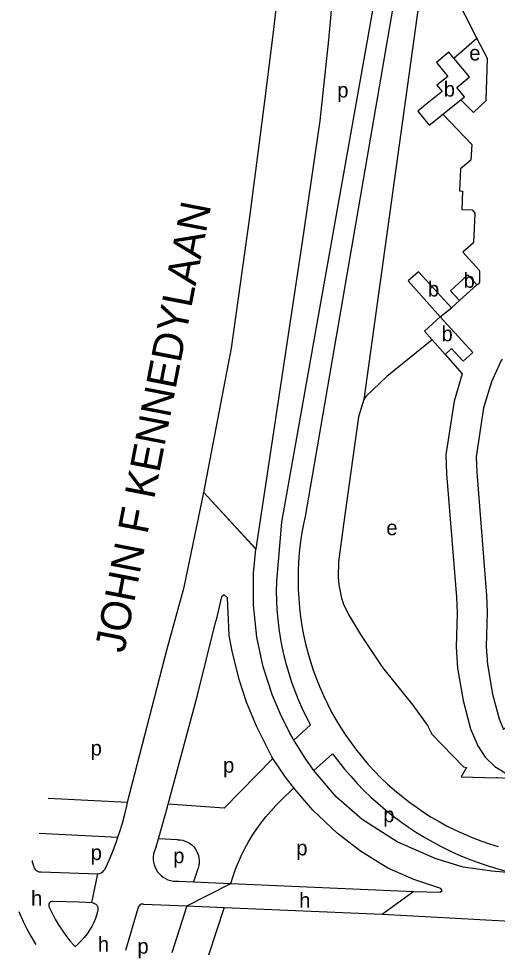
# Model space of a CAD drawing. Extents: x 161773 to 163836, y 384796 to 386521.
# Drawn here: x 161772.9 to 161899.9, y 384853.2 to 385102.4 of the extents above; entities that cross this region are included whole.
import ezdxf

# ---------------------------------------------------------------- set-up
doc = ezdxf.new("R2010")
doc.units = 0
for name, color, linetype in [('BLT_Basislijn', 7, 'Continuous'), ('BLT_Bebouwing', 7, 'Continuous'), ('BLT_Centroide', 7, 'Continuous'), ('BLT_Straatnaam_hoofdweg', 7, 'Continuous'), ('BLT_Vlakafsluiter', 7, 'Continuous')]:
    doc.layers.add(name, color=color, linetype=linetype)

msp = doc.modelspace()

# ---------------------------------------------------------------- linework, layer by layer
at = {"layer": 'BLT_Basislijn'}
for p, q in [((161873.54, 385113.42), (161848.95, 384970.34)), ((161888.38, 385092.02), (161894.55, 385097.32)), ((161889.93, 385027.67), (161887.79, 385025.73)), ((161835.82, 384961.76), (161835.81, 384961.7)), ((161845.96, 384911.03), (161850.33, 384915.09)), ((161851.27, 384903.01), (161856.23, 384907.43)), ((161827.39, 384892.98), (161840.39, 384906.22)), ((161780.74, 384895.67), (161801.8, 384894.59)), ((161827.39, 384892.98), (161812.6, 384894.03)), ((161778.3, 384886.33), (161799.22, 384885.27)), ((161809.4, 384882.73), (161810.01, 384884.88)), ((161815.08, 384884.63), (161810.01, 384884.88)), ((161820.48, 384876.94), (161819.28, 384873.47)), ((161778.81, 384876.1), (161793.91, 384875.57)), ((161815.37, 384873.65), (161819.28, 384873.47)), ((161819.28, 384873.47), (161829.2, 384873.03)), ((161829.2, 384873.03), (161877.83, 384870.87)), ((161806.02, 384867.54), (161817.55, 384867.06)), ((161817.55, 384867.06), (161813.53, 384854.59)), ((161817.55, 384867.06), (161827.45, 384866.65)), ((161827.45, 384866.65), (161823.31, 384853.98)), ((161827.45, 384866.65), (161869.49, 384864.9)), ((161801.3, 384855.35), (161804.59, 384866.47))]:
    msp.add_line(p, q, dxfattribs=at)
for points in [[(161949.14, 385327.14), (161942.55, 385330.53), (161938.43, 385320.55), (161923.2, 385306.75), (161913.58, 385286.21), (161900, 385229.51), (161892.42, 385198.57), (161884.59, 385146.22), (161864.49, 385001.44)], [(161894.55, 385097.32), (161885.32, 385115.47), (161884.66, 385125.98), (161885.84, 385134.74), (161888.36, 385140.63), (161891.73, 385145.18), (161899.3, 385152.42), (161902.89, 385157.22)], [(161857.58, 385124.36), (161855.16, 385096.84), (161852.87, 385075.31), (161848.12, 385043.24), (161835.82, 384961.76)], [(161841.4, 384953.23), (161842.72, 384968.87), (161868.6, 385114.18)], [(161829.37, 385015.04), (161831.79, 385032.09), (161834.13, 385049.14), (161836.4, 385066.2), (161838.58, 385083.28), (161840.69, 385100.36), (161841.72, 385108.98)], [(161890.26, 385080.96), (161893.66, 385077.6), (161896.98, 385080.73), (161897.33, 385091.89), (161894.55, 385097.32)], [(161885.51, 385077.12), (161893.22, 385069.04), (161892.91, 385064.92), (161890.19, 385062.62), (161889.9, 385056.74), (161890.73, 385056.68), (161890.5, 385051.86), (161893.29, 385051.7), (161894.03, 385050.85), (161893.62, 385043.03), (161890.81, 385040.48), (161895.12, 385035.76), (161895.24, 385035.4), (161895.2, 385032.52), (161895.03, 385032.15), (161894.52, 385031.83)], [(161882.69, 385017.21), (161870.64, 385007.53), (161865.04, 385002.24), (161864.49, 385001.44)], [(161822.06, 384976.79), (161829.37, 385015.04)], [(161886.08, 385013.38), (161890.67, 385008.22), (161888.52, 385000.98), (161886.32, 384986.73), (161886.5, 384981.66), (161889.14, 384948.99), (161889.27, 384944.86), (161889.04, 384935.7), (161889.42, 384930.14), (161890.88, 384921.58), (161892.84, 384914.09), (161894.75, 384909.55), (161896.72, 384906.57), (161899.33, 384904.04), (161902.73, 384901.93), (161907.18, 384900.61)], [(161901.22, 385012.12), (161900.86, 385011.6), (161898.39, 385006.11), (161896.34, 384999.22), (161894.34, 384986.25), (161894.49, 384982.12), (161897.13, 384949.44), (161897.27, 384944.89), (161897.04, 384935.87), (161897.37, 384931.09), (161898.71, 384923.27), (161900.44, 384916.67), (161901.61, 384913.87), (161902.51, 384914.77), (161903.09, 384925.99), (161911.95, 384925.55)], [(161864.49, 385001.44), (161863.12, 384996.79), (161859.15, 384968.28)], [(161801.8, 384894.59), (161812.3, 384935.27), (161816.83, 384951.64), (161822.05, 384976.73)], [(161822.05, 384976.73), (161822.06, 384976.79)], [(161848.95, 384970.34), (161848.44, 384967.96), (161848.01, 384965.57), (161847.65, 384963.17), (161847.38, 384960.75), (161847.19, 384958.33), (161847.08, 384955.9), (161847.04, 384953.47), (161847.09, 384951.04), (161847.22, 384948.61), (161847.43, 384946.19), (161847.71, 384943.78), (161848.08, 384941.38), (161848.52, 384938.99), (161849.04, 384936.61), (161849.64, 384934.26), (161850.32, 384931.93), (161851.08, 384929.62), (161851.91, 384927.33), (161852.81, 384925.08), (161853.79, 384922.85), (161854.84, 384920.66), (161855.96, 384918.51), (161857.16, 384916.39), (161858.42, 384914.31), (161859.75, 384912.28), (161861.14, 384910.29), (161862.6, 384908.35), (161864.13, 384906.46), (161865.71, 384904.61), (161867.36, 384902.82), (161869.06, 384901.09), (161870.82, 384899.41), (161872.63, 384897.8), (161874.5, 384896.24), (161876.42, 384894.74), (161878.38, 384893.31), (161880.39, 384891.95), (161882.44, 384890.65), (161884.54, 384889.42), (161886.67, 384888.26), (161888.85, 384887.17), (161891.05, 384886.15), (161893.29, 384885.21), (161895.56, 384884.34), (161897.86, 384883.54), (161900.18, 384882.82)], [(161859.15, 384968.28), (161857.83, 384958.36), (161857.67, 384954.2), (161857.88, 384952.22), (161858.58, 384948.67), (161859.16, 384947.12), (161860.45, 384944.39), (161863.61, 384939.1), (161869.51, 384930.34), (161877.5, 384920.35), (161881.4, 384914.95), (161882.54, 384912.62), (161890.97, 384903.96), (161891.79, 384903.81), (161890.39, 384901.27), (161899.62, 384901.08)], [(161845.96, 384911.03), (161845.76, 384911.36), (161844.79, 384913.07), (161842.35, 384917.91), (161840.3, 384922.92), (161837.83, 384930.54), (161836.12, 384938.37), (161835.21, 384946.82), (161835.19, 384955.31), (161835.81, 384961.7)], [(161850.33, 384915.09), (161849.21, 384917.28), (161848.15, 384919.5), (161847.17, 384921.76), (161846.26, 384924.05), (161845.43, 384926.36), (161844.67, 384928.7), (161843.99, 384931.07), (161843.38, 384933.45), (161842.86, 384935.86), (161842.41, 384938.28), (161842.04, 384940.71), (161841.75, 384943.15), (161841.54, 384945.6), (161841.41, 384948.06), (161841.36, 384950.52), (161841.39, 384952.98), (161841.4, 384953.23)], [(161840.39, 384906.22), (161840.13, 384906.65), (161839.18, 384908.4), (161836.01, 384914.76), (161833.4, 384921.16), (161831.44, 384927.1), (161829.56, 384934.64), (161828.8, 384938.81), (161828.58, 384943.04), (161828.34, 384948.84), (161827.45, 384949.58), (161826.72, 384949.04), (161825.18, 384942.64)], [(161812.6, 384894.03), (161820.25, 384922.61), (161825.18, 384942.64)], [(161851.27, 384903.01), (161849.08, 384905.98), (161846.69, 384909.81), (161845.96, 384911.03)], [(161856.23, 384907.43), (161857.77, 384905.39), (161859.38, 384903.39), (161861.05, 384901.45), (161862.77, 384899.56), (161864.56, 384897.72), (161866.4, 384895.94), (161868.3, 384894.22), (161870.24, 384892.56), (161872.24, 384890.96), (161874.29, 384889.43), (161876.39, 384887.96), (161878.53, 384886.55), (161880.71, 384885.21), (161882.94, 384883.95), (161885.2, 384882.75), (161887.5, 384881.62), (161889.83, 384880.57), (161892.2, 384879.59), (161894.59, 384878.68), (161897.02, 384877.85), (161899.46, 384877.09), (161901.93, 384876.41), (161904.56, 384875.78)], [(161845.94, 384898.35), (161843.99, 384900.88), (161843.54, 384901.48), (161840.39, 384906.22)], [(161904.56, 384875.78), (161898.54, 384876.25), (161890.86, 384877.33), (161883.47, 384879.66), (161873.35, 384884.05), (161864.07, 384889.99), (161857.18, 384896.01), (161851.27, 384903.01)], [(161907.18, 384900.61), (161900, 384901.05), (161899.62, 384901.08)], [(161829.2, 384873.03), (161829.81, 384874.95), (161830.48, 384876.84), (161831.24, 384878.7), (161832.06, 384880.53), (161832.96, 384882.33), (161833.93, 384884.09), (161834.97, 384885.81), (161836.08, 384887.48), (161837.25, 384889.12), (161838.49, 384890.7), (161839.79, 384892.23), (161841.14, 384893.71), (161842.56, 384895.14), (161845.94, 384898.35)], [(161877.83, 384870.87), (161884.78, 384870.69), (161885.3, 384871.13), (161884.95, 384871.72), (161877.77, 384874.06), (161870.86, 384877.1), (161863.65, 384881.58), (161857.48, 384886.34), (161851.01, 384892.45), (161846.19, 384898.03), (161845.94, 384898.35)], [(161799.22, 384885.27), (161799.65, 384886.55), (161800.4, 384888.99), (161801.07, 384891.45), (161801.66, 384893.93), (161801.8, 384894.59)], [(161810.01, 384884.88), (161812.41, 384893.34), (161812.6, 384894.03)], [(161795.92, 384877.05), (161796.96, 384879.38), (161797.93, 384881.74), (161798.83, 384884.13), (161799.22, 384885.27)], [(161815.08, 384884.63), (161815.75, 384884.59), (161816.42, 384884.48), (161817.07, 384884.28), (161817.69, 384884.01), (161818.27, 384883.67), (161818.81, 384883.26), (161819.3, 384882.8), (161819.73, 384882.27), (161820.09, 384881.7), (161820.39, 384881.09), (161820.61, 384880.45), (161820.75, 384879.79), (161820.82, 384879.12), (161820.81, 384878.44), (161820.71, 384877.77), (161820.54, 384877.12), (161820.48, 384876.94)], [(161809.4, 384882.73), (161809.09, 384882.1), (161808.86, 384881.45), (161808.7, 384880.77), (161808.62, 384880.07), (161808.62, 384879.37), (161808.7, 384878.68), (161808.85, 384878), (161809.09, 384877.34), (161809.4, 384876.71), (161809.77, 384876.12), (161810.22, 384875.59), (161810.72, 384875.1), (161811.27, 384874.67), (161811.87, 384874.31), (161812.51, 384874.02), (161813.17, 384873.81), (161813.86, 384873.67), (161814.55, 384873.61), (161815.25, 384873.63), (161815.37, 384873.65)], [(161776.41, 384879.09), (161776.49, 384878.77), (161776.87, 384877.43)], [(161776.87, 384877.43), (161777.02, 384877.07), (161777.24, 384876.75), (161777.52, 384876.49), (161777.85, 384876.28), (161778.22, 384876.15), (161778.6, 384876.09), (161778.81, 384876.1)], [(161793.91, 384875.57), (161794.36, 384875.69), (161794.79, 384875.88), (161795.18, 384876.14), (161795.51, 384876.46), (161795.79, 384876.83), (161795.92, 384877.05)], [(161781.94, 384868.31), (161781.65, 384868.28), (161781.38, 384868.17), (161781.15, 384868), (161780.98, 384867.77), (161780.88, 384867.5), (161780.85, 384867.21), (161780.9, 384866.92), (161781, 384866.71)], [(161781, 384866.71), (161781.74, 384865.13), (161782.55, 384863.59), (161783.44, 384862.08), (161784.39, 384860.62), (161785.4, 384859.21), (161786.49, 384857.84), (161787.63, 384856.52), (161787.83, 384856.3)], [(161781.94, 384868.31), (161788.89, 384868.12), (161792.29, 384867.99)], [(161792.29, 384867.99), (161792.67, 384867.91), (161793.02, 384867.75), (161793.33, 384867.52), (161793.58, 384867.24), (161793.77, 384866.9), (161793.89, 384866.54), (161793.93, 384866.15), (161793.93, 384866.01)], [(161806.02, 384867.54), (161805.72, 384867.57), (161805.42, 384867.53), (161805.14, 384867.41), (161804.91, 384867.21), (161804.73, 384866.97), (161804.62, 384866.69), (161804.59, 384866.47)], [(161772.89, 384865.61), (161773.16, 384864.96), (161774.07, 384862.94), (161775.06, 384860.96), (161776.11, 384859.02), (161777.24, 384857.12), (161777.42, 384856.83)], [(161793.93, 384866.01), (161793.62, 384864.87), (161793.24, 384863.76), (161792.79, 384862.67), (161792.27, 384861.61), (161791.67, 384860.6), (161791.01, 384859.62), (161790.28, 384858.69), (161789.49, 384857.82), (161788.64, 384857), (161787.83, 384856.3)], [(161869.49, 384864.9), (161914.75, 384862.43), (161966.36, 384857.56), (161983.56, 384855.99)]]:
    msp.add_lwpolyline(points, dxfattribs=at)
at = {"layer": 'BLT_Bebouwing'}
for p, q in [((161885.28, 385083.11), (161880.47, 385079.22)), ((161885.51, 385077.12), (161890.26, 385080.96)), ((161883.49, 385075.48), (161885.51, 385077.12)), ((161887.79, 385025.73), (161879.02, 385035.33)), ((161894.52, 385031.83), (161889.93, 385027.67)), ((161884.83, 385023.31), (161887.79, 385025.73)), ((161893.49, 385013.86), (161884.83, 385023.31)), ((161882.69, 385017.21), (161886.08, 385013.38)), ((161890.87, 385011.55), (161893.49, 385013.86))]:
    msp.add_line(p, q, dxfattribs=at)
for points in [[(161888.38, 385092.02), (161887.05, 385093.58), (161883.85, 385090.87), (161886.84, 385087.14), (161883.92, 385084.78), (161885.28, 385083.11)], [(161889.23, 385084.19), (161892.6, 385087.05), (161888.38, 385092.02)], [(161890.26, 385080.96), (161891.22, 385081.74), (161889.23, 385084.19)], [(161880.47, 385079.22), (161878.89, 385077.93), (161881.9, 385074.21), (161883.49, 385075.48)], [(161879.02, 385035.33), (161876.33, 385032.87), (161884.83, 385023.31)], [(161889.93, 385027.67), (161887.54, 385030.29), (161892.13, 385034.46), (161894.52, 385031.83)], [(161884.83, 385023.31), (161880.65, 385019.51), (161882.69, 385017.21)], [(161886.08, 385013.38), (161887.84, 385014.99), (161890.87, 385011.55)]]:
    msp.add_lwpolyline(points, dxfattribs=at)
at = {"layer": 'BLT_Vlakafsluiter'}
for p, q in [((161822.05, 384976.73), (161835.81, 384961.7)), ((161822.06, 384976.79), (161835.82, 384961.76)), ((161792.29, 384867.99), (161793.91, 384875.57)), ((161817.55, 384867.06), (161829.2, 384873.03)), ((161877.83, 384870.87), (161869.49, 384864.9)), ((161787.83, 384856.3), (161787.78, 384856.19))]:
    msp.add_line(p, q, dxfattribs=at)

# ---------------------------------------------------------------- texts
at = {"layer": 'BLT_Centroide'}
for s, p in [('e', (161892.53, 385091.37)), ('b', (161885.75, 385081.78)), ('p', (161857.47, 385081.52)), ('b', (161891.03, 385031.06)), ('b', (161881.55, 385028.74)), ('b', (161885.15, 385016.88)), ('e', (161870.5, 384965.42)), ('p', (161791.99, 384906.96)), ('p', (161827.15, 384902.41)), ('p', (161869.69, 384889.27)), ('p', (161791.99, 384879.23)), ('p', (161813.91, 384878.4)), ('p', (161846.59, 384880.47)), ('h', (161776.16, 384867.1)), ('h', (161847.34, 384866.56)), ('h', (161793.89, 384854.91)), ('p', (161804.4, 384854.4))]:
    msp.add_text(s, height=4, dxfattribs=at).set_placement(p)
at = {"layer": 'BLT_Straatnaam_hoofdweg'}
msp.add_text('JOHN F KENNEDYLAAN', height=7.9999, rotation=79.0094, dxfattribs=at).set_placement((161800.9, 384933.94))

doc.saveas('drawing.dxf')
